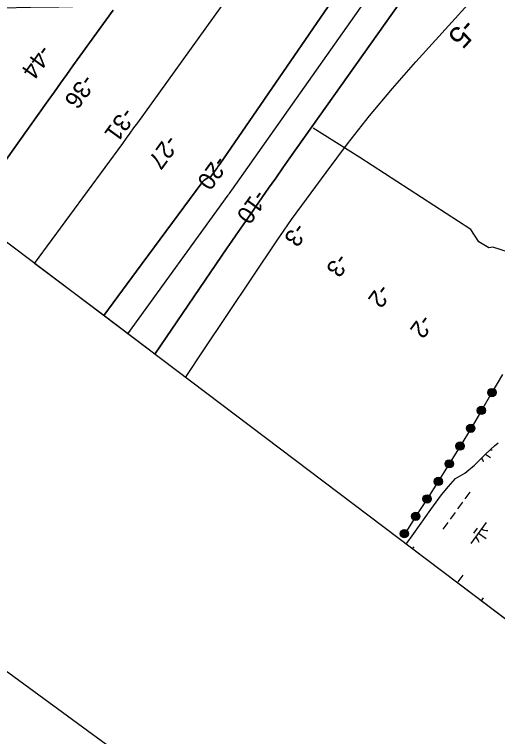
# Model space of a CAD drawing. Extents: x 3905714 to 3926767, y 183354 to 205755.
# Drawn here: x 3913103 to 3914034, y 185892 to 187283 of the extents above; entities that cross this region are included whole.
import ezdxf

# ---------------------------------------------------------------- set-up
doc = ezdxf.new("R2010")
doc.units = 0
for name, color, linetype in [('V-ANNO-SYMB', 7, 'Continuous'), ('V-GRID-FRAM', 7, 'Continuous'), ('V-GRID-MAJR', 7, 'Continuous'), ('V-LEVE-TOET', 7, 'Continuous'), ('V-RIVR-RANG', 7, 'Continuous'), ('V-RRAP-FSHR', 7, 'Continuous'), ('V-TOPO-DPTH', 7, 'Continuous'), ('V-TOPO-MINR', 7, 'Continuous'), ('V-TOPO-MINR-IDEN', 7, 'Continuous'), ('V-TOPO-SHOR', 7, 'Continuous'), ('V-WETL-SWMP', 7, 'Continuous')]:
    doc.layers.add(name, color=color, linetype=linetype)

msp = doc.modelspace()

# ---------------------------------------------------------------- linework, layer by layer
at = {"layer": 'V-ANNO-SYMB'}
msp.add_lwpolyline([(3916223.9, 204226), (3906447.8, 190882.4), (3915690.8, 184110.5), (3925467, 197454.1), (3916223.9, 204226)], dxfattribs=at)
at = {"layer": 'V-GRID-FRAM'}
msp.add_lwpolyline([(3924287.8, 196971.1), (3915521.4, 185005.6), (3909313.3, 189695.8), (3918205.9, 201877.9), (3924287.8, 196971.1)], dxfattribs=at)
at = {"layer": 'V-GRID-MAJR'}
msp.add_spline([(3911382.6, 187267), (3914884.1, 187327.4), (3918088.4, 187383)], degree=3, dxfattribs=at)
at = {"layer": 'V-LEVE-TOET'}
msp.add_lwpolyline([(3914126.5, 186773.1), (3914054.8, 186825.3), (3914024.3, 186835.1), (3914016.8, 186833.3), (3913997.5, 186845.2), (3913981.9, 186868.6), (3913768.4, 187007.8), (3913678.5, 187064.4)], dxfattribs=at)
at = {"layer": 'V-RRAP-FSHR'}
for points in [[(3914043, 186589.2), (3914022.7, 186554.7), (3914002.5, 186520.2), (3913982.9, 186485.8), (3913961.3, 186451.6), (3913940.5, 186417.4), (3913919.5, 186383.4), (3913897.8, 186349.8), (3913876, 186316.3), (3913854.9, 186282.8)], [(3914024.4, 186561.8), (3914026.2, 186560.8), (3914028.7, 186558.7), (3914029.7, 186556.4), (3914029.7, 186553.1), (3914028.5, 186550.7), (3914026.2, 186548.3), (3914023.3, 186547.8), (3914021, 186547.7), (3914018.5, 186549), (3914016.8, 186550.8), (3914015.9, 186553), (3914015.7, 186555.2), (3914016.3, 186557.7), (3914018.6, 186560.4), (3914021.5, 186561.6), (3914023.9, 186561.7), (3914026.5, 186559.2), (3914028.4, 186557), (3914028.6, 186554.2), (3914027.6, 186551.1), (3914025.2, 186549.2), (3914022.2, 186548.8), (3914019.5, 186549.6), (3914017.4, 186551.8), (3914016.7, 186554.7), (3914017.8, 186558), (3914020.2, 186560), (3914022.9, 186560.7), (3914025.9, 186559), (3914027.3, 186556.7), (3914027.6, 186553.8), (3914026.5, 186551.3), (3914024.2, 186549.9), (3914021.5, 186549.7), (3914018.9, 186551.5), (3914017.8, 186554.1), (3914019, 186557.9), (3914021.3, 186559.5), (3914023.2, 186559.5), (3914025.5, 186557.6), (3914026.7, 186554.9), (3914026.2, 186552.6), (3914023.8, 186550.7), (3914021.4, 186550.9), (3914019.1, 186552.9), (3914019, 186555.3), (3914020.1, 186557.4), (3914021.8, 186558.7), (3914023.9, 186558.2), (3914025, 186556.6), (3914025.8, 186554.4), (3914024.8, 186552.6), (3914023.1, 186551.7), (3914021, 186552.2), (3914020, 186553.8), (3914020, 186555.6), (3914021.4, 186557.3), (3914022.7, 186557.5), (3914024.1, 186556.1), (3914024.6, 186554.3), (3914023.9, 186553), (3914022.4, 186552.8), (3914020.8, 186553.8), (3914020.9, 186555.5), (3914021.9, 186556.4), (3914023.4, 186555.7), (3914023.6, 186554), (3914022.5, 186553.7), (3914021.8, 186554.6), (3914022.1, 186555.5), (3914022.8, 186554.7)], [(3914004.1, 186527.3), (3914006, 186526.4), (3914008.4, 186524.2), (3914009.5, 186521.9), (3914009.5, 186518.7), (3914008.3, 186516.2), (3914005.9, 186513.8), (3914003.1, 186513.3), (3914000.8, 186513.2), (3913998.3, 186514.5), (3913996.5, 186516.3), (3913995.6, 186518.5), (3913995.4, 186520.7), (3913996.1, 186523.2), (3913998.3, 186525.9), (3914001.3, 186527.1), (3914003.7, 186527.2), (3914006.2, 186524.8), (3914008.1, 186522.5), (3914008.4, 186519.7), (3914007.3, 186516.7), (3914004.9, 186514.7), (3914001.9, 186514.3), (3913999.3, 186515.1), (3913997.2, 186517.3), (3913996.5, 186520.2), (3913997.6, 186523.5), (3914000, 186525.5), (3914002.7, 186526.2), (3914005.6, 186524.5), (3914007.1, 186522.2), (3914007.4, 186519.4), (3914006.2, 186516.8), (3914004, 186515.4), (3914001.2, 186515.2), (3913998.7, 186517), (3913997.6, 186519.6), (3913998.7, 186523.4), (3914001, 186525), (3914002.9, 186525), (3914005.3, 186523.1), (3914006.5, 186520.4), (3914005.9, 186518.1), (3914003.5, 186516.2), (3914001.2, 186516.4), (3913998.8, 186518.4), (3913998.7, 186520.8), (3913999.8, 186522.9), (3914001.6, 186524.2), (3914003.6, 186523.7), (3914004.7, 186522.1), (3914005.5, 186519.9), (3914004.6, 186518.1), (3914002.8, 186517.2), (3914000.7, 186517.7), (3913999.7, 186519.3), (3913999.7, 186521.1), (3914001.1, 186522.8), (3914002.5, 186523.1), (3914003.8, 186521.6), (3914004.4, 186519.8), (3914003.7, 186518.5), (3914002.1, 186518.3), (3914000.6, 186519.3), (3914000.7, 186521), (3914001.6, 186521.9), (3914003.1, 186521.2), (3914003.4, 186519.6), (3914002.2, 186519.2), (3914001.6, 186520.1), (3914001.8, 186521), (3914002.5, 186520.2)], [(3913983.8, 186492.9), (3913985.7, 186491.9), (3913988.1, 186489.7), (3913989.1, 186487.3), (3913989.1, 186484.1), (3913987.8, 186481.7), (3913985.4, 186479.3), (3913982.6, 186478.9), (3913980.3, 186478.8), (3913977.8, 186480.1), (3913976.1, 186482), (3913975.2, 186484.2), (3913975, 186486.4), (3913975.7, 186488.9), (3913978.1, 186491.5), (3913981, 186492.7), (3913983.4, 186492.8), (3913985.9, 186490.3), (3913987.8, 186488), (3913988, 186485.2), (3913986.9, 186482.2), (3913984.5, 186480.3), (3913981.5, 186479.9), (3913978.8, 186480.7), (3913976.7, 186483), (3913976.1, 186485.9), (3913977.2, 186489.2), (3913979.7, 186491.1), (3913982.4, 186491.7), (3913985.3, 186490.1), (3913986.7, 186487.7), (3913987, 186484.9), (3913985.8, 186482.4), (3913983.5, 186481), (3913980.8, 186480.8), (3913978.2, 186482.7), (3913977.2, 186485.3), (3913978.4, 186489), (3913980.7, 186490.6), (3913982.6, 186490.6), (3913984.9, 186488.6), (3913986.1, 186486), (3913985.5, 186483.6), (3913983.1, 186481.7), (3913980.7, 186482), (3913978.4, 186484), (3913978.3, 186486.4), (3913979.5, 186488.6), (3913981.3, 186489.8), (3913983.3, 186489.3), (3913984.4, 186487.7), (3913985.1, 186485.5), (3913984.1, 186483.6), (3913982.4, 186482.7), (3913980.3, 186483.3), (3913979.3, 186485), (3913979.4, 186486.7), (3913980.8, 186488.4), (3913982.1, 186488.6), (3913983.5, 186487.2), (3913984, 186485.3), (3913983.3, 186484.1), (3913981.7, 186483.9), (3913980.2, 186484.9), (3913980.3, 186486.6), (3913981.3, 186487.5), (3913982.7, 186486.7), (3913983, 186485.1), (3913981.9, 186484.8), (3913981.2, 186485.7), (3913981.4, 186486.6), (3913982.1, 186485.8)], [(3913963, 186458.7), (3913964.9, 186457.7), (3913967.3, 186455.5), (3913968.3, 186453.2), (3913968.3, 186450), (3913967, 186447.5), (3913964.6, 186445.2), (3913961.8, 186444.7), (3913959.5, 186444.6), (3913957, 186446), (3913955.3, 186447.8), (3913954.4, 186450), (3913954.2, 186452.2), (3913954.9, 186454.8), (3913957.2, 186457.4), (3913960.2, 186458.6), (3913962.6, 186458.6), (3913965.1, 186456.1), (3913967, 186453.8), (3913967.2, 186451), (3913966.1, 186448), (3913963.6, 186446.1), (3913960.6, 186445.7), (3913958, 186446.6), (3913955.9, 186448.8), (3913955.3, 186451.8), (3913956.4, 186455), (3913958.9, 186457), (3913961.6, 186457.6), (3913964.5, 186455.9), (3913965.9, 186453.5), (3913966.2, 186450.7), (3913965, 186448.2), (3913962.7, 186446.8), (3913960, 186446.7), (3913957.4, 186448.5), (3913956.4, 186451.1), (3913957.6, 186454.8), (3913959.9, 186456.4), (3913961.8, 186456.5), (3913964.1, 186454.4), (3913965.3, 186451.8), (3913964.7, 186449.4), (3913962.3, 186447.6), (3913959.9, 186447.8), (3913957.6, 186449.8), (3913957.5, 186452.3), (3913958.7, 186454.4), (3913960.5, 186455.6), (3913962.5, 186455.1), (3913963.6, 186453.5), (3913964.3, 186451.3), (3913963.3, 186449.5), (3913961.6, 186448.6), (3913959.5, 186449.2), (3913958.5, 186450.8), (3913958.6, 186452.6), (3913960, 186454.3), (3913961.3, 186454.5), (3913962.7, 186453), (3913963.2, 186451.2), (3913962.5, 186449.9), (3913960.9, 186449.7), (3913959.4, 186450.8), (3913959.5, 186452.4), (3913960.5, 186453.3), (3913961.9, 186452.6), (3913962.2, 186451), (3913961, 186450.7), (3913960.4, 186451.6), (3913960.6, 186452.4), (3913961.3, 186451.6)], [(3913942.2, 186424.5), (3913944, 186423.6), (3913946.5, 186421.4), (3913947.5, 186419), (3913947.4, 186415.8), (3913946.2, 186413.4), (3913943.8, 186411), (3913940.9, 186410.6), (3913938.7, 186410.5), (3913936.2, 186411.8), (3913934.5, 186413.7), (3913933.6, 186415.9), (3913933.4, 186418.1), (3913934.1, 186420.6), (3913936.4, 186423.2), (3913939.4, 186424.4), (3913941.8, 186424.4), (3913944.3, 186422), (3913946.2, 186419.7), (3913946.4, 186416.9), (3913945.3, 186413.8), (3913942.8, 186411.9), (3913939.8, 186411.5), (3913937.2, 186412.4), (3913935.1, 186414.7), (3913934.5, 186417.6), (3913935.6, 186420.9), (3913938.1, 186422.8), (3913940.8, 186423.4), (3913943.7, 186421.8), (3913945.1, 186419.4), (3913945.4, 186416.5), (3913944.1, 186414), (3913941.9, 186412.6), (3913939.2, 186412.5), (3913936.6, 186414.4), (3913935.6, 186417), (3913936.7, 186420.7), (3913939.1, 186422.3), (3913941, 186422.3), (3913943.3, 186420.3), (3913944.5, 186417.6), (3913943.9, 186415.3), (3913941.5, 186413.4), (3913939.1, 186413.7), (3913936.8, 186415.7), (3913936.7, 186418.1), (3913937.9, 186420.2), (3913939.6, 186421.5), (3913941.7, 186421), (3913942.8, 186419.3), (3913943.5, 186417.1), (3913942.5, 186415.3), (3913940.8, 186414.4), (3913938.7, 186415), (3913937.7, 186416.7), (3913937.8, 186418.4), (3913939.2, 186420.1), (3913940.5, 186420.3), (3913941.9, 186418.9), (3913942.4, 186417), (3913941.7, 186415.8), (3913940.1, 186415.6), (3913938.6, 186416.6), (3913938.7, 186418.3), (3913939.7, 186419.2), (3913941.1, 186418.4), (3913941.4, 186416.8), (3913940.2, 186416.5), (3913939.6, 186417.4), (3913939.8, 186418.2), (3913940.5, 186417.5)], [(3913921.4, 186390.5), (3913923.2, 186389.4), (3913925.6, 186387.2), (3913926.5, 186384.8), (3913926.4, 186381.6), (3913925.1, 186379.2), (3913922.6, 186376.9), (3913919.8, 186376.5), (3913917.5, 186376.5), (3913915, 186377.9), (3913913.4, 186379.8), (3913912.6, 186382), (3913912.4, 186384.2), (3913913.2, 186386.7), (3913915.6, 186389.3), (3913918.5, 186390.4), (3913920.9, 186390.4), (3913923.4, 186387.8), (3913925.2, 186385.5), (3913925.3, 186382.7), (3913924.2, 186379.7), (3913921.7, 186377.9), (3913918.7, 186377.5), (3913916, 186378.5), (3913914, 186380.8), (3913913.5, 186383.7), (3913914.7, 186386.9), (3913917.2, 186388.8), (3913919.9, 186389.4), (3913922.8, 186387.6), (3913924.1, 186385.2), (3913924.3, 186382.4), (3913923, 186379.9), (3913920.8, 186378.6), (3913918, 186378.5), (3913915.5, 186380.4), (3913914.5, 186383.1), (3913915.8, 186386.7), (3913918.2, 186388.3), (3913920.1, 186388.2), (3913922.4, 186386.2), (3913923.5, 186383.5), (3913922.8, 186381.2), (3913920.3, 186379.4), (3913918, 186379.7), (3913915.7, 186381.8), (3913915.7, 186384.2), (3913916.9, 186386.3), (3913918.7, 186387.4), (3913920.7, 186386.9), (3913921.8, 186385.2), (3913922.5, 186383), (3913921.4, 186381.2), (3913919.7, 186380.4), (3913917.6, 186381), (3913916.6, 186382.7), (3913916.8, 186384.5), (3913918.2, 186386.1), (3913919.6, 186386.3), (3913920.9, 186384.8), (3913921.4, 186382.9), (3913920.6, 186381.7), (3913919, 186381.6), (3913917.5, 186382.6), (3913917.7, 186384.3), (3913918.7, 186385.2), (3913920.1, 186384.4), (3913920.3, 186382.7), (3913919.2, 186382.5), (3913918.5, 186383.4), (3913918.8, 186384.2), (3913919.5, 186383.4)], [(3913899.7, 186356.8), (3913901.5, 186355.8), (3913903.9, 186353.6), (3913904.9, 186351.2), (3913904.7, 186348), (3913903.4, 186345.6), (3913901, 186343.3), (3913898.1, 186342.9), (3913895.8, 186342.9), (3913893.4, 186344.3), (3913891.7, 186346.2), (3913890.9, 186348.4), (3913890.8, 186350.6), (3913891.5, 186353.1), (3913893.9, 186355.6), (3913896.9, 186356.8), (3913899.3, 186356.7), (3913901.7, 186354.2), (3913903.5, 186351.9), (3913903.7, 186349.1), (3913902.5, 186346.1), (3913900, 186344.2), (3913897, 186343.9), (3913894.4, 186344.8), (3913892.4, 186347.2), (3913891.8, 186350.1), (3913893, 186353.3), (3913895.5, 186355.2), (3913898.3, 186355.8), (3913901.1, 186354), (3913902.5, 186351.6), (3913902.6, 186348.8), (3913901.4, 186346.3), (3913899.1, 186344.9), (3913896.4, 186344.9), (3913893.9, 186346.8), (3913892.9, 186349.5), (3913894.1, 186353.1), (3913896.6, 186354.6), (3913898.5, 186354.6), (3913900.7, 186352.5), (3913901.8, 186349.9), (3913901.1, 186347.5), (3913898.7, 186345.7), (3913896.3, 186346), (3913894.1, 186348.1), (3913894.1, 186350.5), (3913895.2, 186352.7), (3913897.1, 186353.8), (3913899.1, 186353.3), (3913900.1, 186351.6), (3913900.8, 186349.4), (3913899.8, 186347.6), (3913898, 186346.8), (3913895.9, 186347.4), (3913895, 186349.1), (3913895.1, 186350.8), (3913896.6, 186352.5), (3913897.9, 186352.7), (3913899.2, 186351.2), (3913899.7, 186349.3), (3913898.9, 186348.1), (3913897.4, 186347.9), (3913895.9, 186349), (3913896, 186350.6), (3913897, 186351.5), (3913898.5, 186350.7), (3913898.7, 186349.1), (3913897.5, 186348.9), (3913896.9, 186349.8), (3913897.1, 186350.6), (3913897.8, 186349.8)], [(3913877.9, 186323.3), (3913879.7, 186322.3), (3913882.1, 186320), (3913883, 186317.6), (3913882.9, 186314.4), (3913881.5, 186312), (3913879.1, 186309.8), (3913876.2, 186309.4), (3913873.9, 186309.4), (3913871.5, 186310.8), (3913869.8, 186312.7), (3913869, 186314.9), (3913868.9, 186317.1), (3913869.7, 186319.6), (3913872.1, 186322.2), (3913875.1, 186323.3), (3913877.5, 186323.2), (3913879.9, 186320.7), (3913881.7, 186318.3), (3913881.8, 186315.5), (3913880.6, 186312.5), (3913878.1, 186310.7), (3913875.1, 186310.4), (3913872.5, 186311.3), (3913870.5, 186313.7), (3913870, 186316.6), (3913871.2, 186319.8), (3913873.7, 186321.7), (3913876.4, 186322.2), (3913879.3, 186320.5), (3913880.6, 186318.1), (3913880.8, 186315.2), (3913879.5, 186312.8), (3913877.2, 186311.4), (3913874.5, 186311.4), (3913872, 186313.3), (3913871, 186316), (3913872.3, 186319.6), (3913874.7, 186321.1), (3913876.6, 186321.1), (3913878.9, 186319), (3913880, 186316.4), (3913879.3, 186314), (3913876.8, 186312.2), (3913874.5, 186312.5), (3913872.2, 186314.6), (3913872.2, 186317), (3913873.4, 186319.2), (3913875.2, 186320.3), (3913877.2, 186319.8), (3913878.3, 186318.1), (3913879, 186315.9), (3913877.9, 186314.1), (3913876.2, 186313.2), (3913874.1, 186313.9), (3913873.1, 186315.6), (3913873.3, 186317.3), (3913874.7, 186319), (3913876.1, 186319.1), (3913877.4, 186317.6), (3913877.8, 186315.8), (3913877.1, 186314.6), (3913875.5, 186314.4), (3913874, 186315.5), (3913874.2, 186317.1), (3913875.2, 186318), (3913876.6, 186317.2), (3913876.8, 186315.6), (3913875.7, 186315.3), (3913875, 186316.3), (3913875.3, 186317.1), (3913876, 186316.3)], [(3913856.1, 186289.8), (3913857.9, 186288.8), (3913860.2, 186286.5), (3913861.2, 186284.1), (3913861, 186280.9), (3913859.7, 186278.5), (3913857.2, 186276.3), (3913854.3, 186275.9), (3913852.1, 186275.9), (3913849.6, 186277.3), (3913848, 186279.2), (3913847.2, 186281.4), (3913847.1, 186283.6), (3913847.8, 186286.1), (3913850.2, 186288.7), (3913853.2, 186289.8), (3913855.6, 186289.7), (3913858, 186287.2), (3913859.9, 186284.8), (3913860, 186282), (3913858.8, 186279), (3913856.3, 186277.2), (3913853.3, 186276.9), (3913850.6, 186277.8), (3913848.6, 186280.2), (3913848.1, 186283.1), (3913849.3, 186286.3), (3913851.8, 186288.2), (3913854.6, 186288.8), (3913857.5, 186287), (3913858.8, 186284.6), (3913858.9, 186281.7), (3913857.7, 186279.3), (3913855.4, 186277.9), (3913852.6, 186277.9), (3913850.1, 186279.8), (3913849.2, 186282.5), (3913850.5, 186286.1), (3913852.9, 186287.6), (3913854.8, 186287.6), (3913857, 186285.5), (3913858.1, 186282.9), (3913857.4, 186280.5), (3913855, 186278.7), (3913852.6, 186279), (3913850.4, 186281.1), (3913850.4, 186283.5), (3913851.6, 186285.7), (3913853.4, 186286.8), (3913855.4, 186286.3), (3913856.5, 186284.6), (3913857.1, 186282.4), (3913856.1, 186280.6), (3913854.3, 186279.7), (3913852.2, 186280.4), (3913851.3, 186282.1), (3913851.4, 186283.8), (3913852.9, 186285.5), (3913854.2, 186285.6), (3913855.5, 186284.2), (3913856, 186282.3), (3913855.2, 186281.1), (3913853.7, 186280.9), (3913852.2, 186282), (3913852.3, 186283.6), (3913853.3, 186284.5), (3913854.8, 186283.7), (3913855, 186282.1), (3913853.8, 186281.8), (3913853.2, 186282.8), (3913853.5, 186283.6), (3913854.1, 186282.8)]]:
    msp.add_lwpolyline(points, dxfattribs=at)
for centre in [(3914022.7, 186554.7), (3914002.5, 186520.2), (3913982.1, 186485.8), (3913961.3, 186451.6), (3913940.5, 186417.4), (3913919.5, 186383.4), (3913897.8, 186349.8), (3913876, 186316.3), (3913854.1, 186282.8)]:
    msp.add_circle(centre, 8, dxfattribs=at)
at = {"layer": 'V-TOPO-DPTH'}
for p, q in [((3913274.8, 186702.9), (3913141.4, 186803.6)), ((3913373.1, 186628.6), (3913274.8, 186702.9))]:
    msp.add_line(p, q, dxfattribs=at)
for points in [[(3913274.8, 186702.9), (3913337.9, 186788.9), (3913463.5, 186958.9), (3913465.8, 186961.5), (3913468.4, 186963.9), (3913471.2, 186965.9), (3913474.3, 186967.5), (3913480.3, 186970.2), (3913480.6, 186970.3), (3913481, 186970.7), (3913481.2, 186970.9), (3913486.8, 186978.5), (3913489.7, 186982.6), (3913492.6, 186986.7), (3913495.5, 186990.8), (3913498.4, 186995), (3913928.9, 187621.6)], [(3913928.9, 187621.6), (3913498.4, 186995), (3913495.5, 186990.8), (3913492.6, 186986.7), (3913489.7, 186982.6), (3913486.8, 186978.5), (3913481.2, 186970.9), (3913481, 186970.7), (3913480.6, 186970.3), (3913480.3, 186970.2), (3913474.3, 186967.5), (3913471.2, 186965.9), (3913468.4, 186963.9), (3913465.8, 186961.5), (3913463.5, 186958.9), (3913337.9, 186788.9), (3913274.8, 186702.9)], [(3914032.5, 187569.7), (3913647.4, 187026.6), (3913633.6, 187007.1), (3913619.8, 186987.5), (3913606.1, 186968), (3913592.4, 186948.4), (3913567.8, 186913.1), (3913566.5, 186911.1), (3913563.8, 186907.2), (3913562.4, 186905.3), (3913547.6, 186884.1), (3913538.9, 186871.5), (3913530.1, 186858.9), (3913521.5, 186846.3), (3913512.8, 186833.6), (3913373.1, 186628.6)], [(3913141.4, 186803.6), (3913311.2, 187034.8), (3913318.5, 187044.7), (3913325.7, 187054.7), (3913332.9, 187064.7), (3913340.1, 187074.7), (3913673.5, 187539)], [(3913141.4, 186803.6), (3913311.2, 187034.8), (3913318.5, 187044.7), (3913325.7, 187054.7), (3913332.9, 187064.7), (3913340.1, 187074.7), (3913673.5, 187539)], [(3913292.6, 187291.4), (3913215.3, 187184.1), (3913203.4, 187167.6), (3913191.5, 187151), (3913179.7, 187134.4), (3913167.8, 187117.7), (3913109.4, 187035.5), (3913068.1, 186978), (3913026.5, 186920.7), (3913012.1, 186901.3)], [(3913292.6, 187291.4), (3913215.3, 187184.1), (3913203.4, 187167.6), (3913191.5, 187151), (3913179.7, 187134.4), (3913167.8, 187117.7), (3913109.4, 187035.5), (3913068.1, 186978), (3913026.5, 186920.7), (3913012.1, 186901.3)]]:
    msp.add_lwpolyline(points, dxfattribs=at)
at = {"layer": 'V-TOPO-MINR'}
for points in [[(3913274.8, 186702.9), (3913337.9, 186788.9), (3913463.5, 186958.9), (3913465.8, 186961.5), (3913468.4, 186963.9), (3913471.2, 186965.9), (3913474.3, 186967.5), (3913480.3, 186970.2), (3913480.6, 186970.3), (3913481, 186970.7), (3913481.2, 186970.9), (3913486.8, 186978.5), (3913489.7, 186982.6), (3913492.6, 186986.7), (3913495.5, 186990.8), (3913498.4, 186995), (3913928.9, 187621.6)], [(3913373.1, 186628.6), (3913512.8, 186833.6), (3913521.5, 186846.3), (3913530.1, 186858.9), (3913538.9, 186871.5), (3913547.6, 186884.1), (3913562.4, 186905.3), (3913563.8, 186907.2), (3913566.5, 186911.1), (3913567.8, 186913.1), (3913592.4, 186948.4), (3913606.1, 186968), (3913619.8, 186987.5), (3913633.6, 187007.1), (3913647.4, 187026.6), (3914032.5, 187569.7)], [(3913141.4, 186803.6), (3913311.2, 187034.8), (3913318.5, 187044.7), (3913325.7, 187054.7), (3913332.9, 187064.7), (3913340.1, 187074.7), (3913673.5, 187539)], [(3913321.1, 186667.9), (3913514.5, 186934.9), (3913515.4, 186936.1), (3913517.1, 186938.5), (3913519.7, 186942.2), (3913521.4, 186944.6), (3913868.1, 187436.2)], [(3913432.4, 186583.8), (3913466.1, 186635.2), (3913608.2, 186847.1), (3913615.2, 186857.5), (3913622.2, 186867.7), (3913629.4, 186877.9), (3913636.7, 186888), (3913703.1, 186979), (3913744.4, 187033.9), (3913786.9, 187087.9), (3913831.1, 187140.5), (3913876.4, 187192.2), (3914046.6, 187380.1)], [(3913012.1, 186901.3), (3913026.5, 186920.7), (3913068.1, 186978), (3913109.4, 187035.5), (3913167.8, 187117.7), (3913179.7, 187134.4), (3913191.5, 187151), (3913203.4, 187167.6), (3913215.3, 187184.1), (3913292.6, 187291.4)]]:
    msp.add_lwpolyline(points, dxfattribs=at)
at = {"layer": 'V-TOPO-SHOR'}
for points in [[(3914020.1, 186444.7), (3914027.7, 186452.3), (3914034.9, 186457.9)], [(3913857.7, 186262.5), (3913872.6, 186283.1), (3913905.2, 186329.3), (3913925.6, 186357.5), (3913939, 186373.6), (3913952.7, 186389), (3913970.7, 186399.5), (3913989.1, 186414.9), (3914009.8, 186435.4), (3914020.1, 186444.7)]]:
    msp.add_lwpolyline(points, dxfattribs=at)
at = {"layer": 'V-WETL-SWMP'}
for p, q in [((3914020.1, 186444.7), (3914027.7, 186452.3)), ((3914027.7, 186452.3), (3914034.9, 186457.9)), ((3913989.1, 186414.9), (3914009.8, 186435.4)), ((3914009.8, 186435.4), (3914020.1, 186444.7)), ((3914010.7, 186436.2), (3914020.1, 186429.3)), ((3913970.7, 186399.5), (3913989.1, 186414.9)), ((3913952.7, 186389), (3913970.7, 186399.5)), ((3913939, 186373.6), (3913952.7, 186389)), ((3913925.6, 186357.5), (3913939, 186373.6)), ((3913980.3, 186362.6), (3913970.9, 186349.7)), ((3913905.2, 186329.3), (3913925.6, 186357.5)), ((3913966.2, 186343.3), (3913956.7, 186330.4)), ((3913872.6, 186283.1), (3913905.2, 186329.3)), ((3913952, 186323.9), (3913942.5, 186311)), ((3913937.8, 186304.5), (3913928.3, 186291.6)), ((3914012, 186304.2), (3913982.4, 186263.9)), ((3913994.5, 186293.5), (3913987.4, 186283.8)), ((3913857.7, 186262.5), (3913872.6, 186283.1)), ((3913997.2, 186284.1), (3914011.7, 186273.4)), ((3914859.3, 185505.8), (3913857.7, 186262.5)), ((3913872, 186257.7), (3913869.2, 186253.8)), ((3913966.6, 186202.9), (3913957.1, 186190)), ((3914006.2, 186159.4), (3914001.9, 186153.5))]:
    msp.add_line(p, q, dxfattribs=at)
for centre, start, end in [((3914022.1, 186462.1), 263.1554, 274.5436), ((3913989.4, 186417.6), 13, 39.2787), ((3914013.7, 186306.2), 233, 274.5436), ((3913981.1, 186261.6), 13, 54.5436)]:
    msp.add_arc(centre, 17.6, start, end, dxfattribs=at)

# ---------------------------------------------------------------- texts
at = {"layer": 'V-RIVR-RANG'}
for s, rotation, p in [('-44', 234.006, (3913152.2, 187227.3)), ('-36', 234.006, (3913235.2, 187170.3)), ('-31', 234.006, (3913312.3, 187106.6)), ('-27', 234.006, (3913396.1, 187053.7)), ('-20', 233.8683, (3913491.1, 187013.9)), ('-10', 233.8683, (3913567, 186948.3)), ('-3', 233.8683, (3913644.1, 186884.3)), ('-3', 233.8683, (3913725.1, 186825.5)), ('-2', 233.8683, (3913805.8, 186766.5)), ('-2', 233.8683, (3913886.7, 186707.8))]:
    msp.add_text(s, height=33.5, rotation=rotation, dxfattribs=at).set_placement(p)
at = {"layer": 'V-TOPO-MINR-IDEN'}
msp.add_text('-5', height=41.5, rotation=227.8368, dxfattribs=at).set_placement((3913968.7, 187278.7))

doc.saveas('drawing.dxf')
